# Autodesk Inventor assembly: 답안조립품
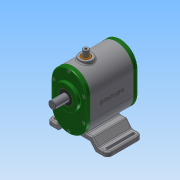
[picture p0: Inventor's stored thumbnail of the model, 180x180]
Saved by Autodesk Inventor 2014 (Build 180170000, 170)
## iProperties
Created: 2018-07
Part Number: 답안조립품
Document SubType Name: Assembly
Designer: SEO-12
Author: SEO-12
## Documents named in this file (14)
- C:\Users\SEO-12\Desktop\380708V1015\답안조립품.iam
- C:\Users\SEO-12\Desktop\380708V1015\본체.ipt
- C:\Users\SEO-12\Desktop\380708V1015\가변스프링.ipt
- C:\Users\SEO-12\Desktop\380708V1015\뒤커버.ipt
- C:\Users\SEO-12\Desktop\380708V1015\메인축.ipt
- C:\Users\SEO-12\Desktop\380708V1015\베어링 608.ipt
- C:\Users\SEO-12\Desktop\380708V1015\베어링 6003.ipt
- C:\Users\SEO-12\Desktop\380708V1015\볼트 M4.ipt
- C:\Users\SEO-12\Desktop\380708V1015\부시.ipt
- C:\Users\SEO-12\Desktop\380708V1015\서브축.ipt
- C:\Users\SEO-12\Desktop\380708V1015\슬라이더.ipt
- C:\Users\SEO-12\Desktop\380708V1015\앞커버.ipt
- C:\Users\SEO-12\Desktop\380708V1015\오일 실 8 22 7.ipt
- C:\Users\SEO-12\Desktop\380708V1015\오일 실 17 32 8.ipt
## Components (1 placed, 1 different names)
1. 가변스프링:1
